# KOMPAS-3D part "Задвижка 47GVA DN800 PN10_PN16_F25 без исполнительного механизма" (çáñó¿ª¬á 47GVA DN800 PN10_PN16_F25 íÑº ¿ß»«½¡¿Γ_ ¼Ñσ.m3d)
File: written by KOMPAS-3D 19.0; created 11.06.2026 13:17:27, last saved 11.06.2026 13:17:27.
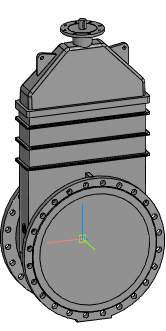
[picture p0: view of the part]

Document properties: Автор: Евгений; Полное имя файла: Z:\3.Личные\kachalov\001_3d для проектировщиков\2.2 Тип 47GVA, 47GVA.Z\_stp\_stp_Задвижка 47GVA DN40-DN1000 без исп.мех\Задвижка 47GVA DN800 PN10_PN16_F25 без исполнит_ мех.m3d

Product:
- Part/product: Задвижка 47GVA DN800 PN10_PN16_F25 без исполнительного механизма

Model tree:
1. Операция без истории:1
